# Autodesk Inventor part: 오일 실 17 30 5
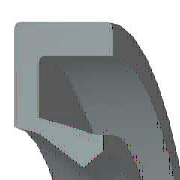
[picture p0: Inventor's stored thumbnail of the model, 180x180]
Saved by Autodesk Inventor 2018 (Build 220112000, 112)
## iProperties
Created: 2012-02
Part Number: 오일 실 17 30 5
Material: 고무
Description: 오일 실 - 스프링 장착, 비스프링, 고무 덮개 G
Document SubType Name: Modeling
Standard: JIS B 2402
Designer: mduedu
Standards Organization: JIS
Language: ko-KR
Size Designation: 17 30 5 A
Categories: <MemberInstance><Categories><Category DisplayName="샤프트 부품" InternalName="7f7aeb1f-a693-4053-b835-cee3144e0d98" Mnemonic="SHFT"><Category DisplayName="실링" Intern
Density: 0.93 g/cm^3
Appearance: 고무 - 검은색 - 버전 1.1
Mass: 1.22959 g
Surface Area: 18.6191 cm^2
Volume: 1.32214 cm^3
IsCustomPart: 1
Author: mduedu
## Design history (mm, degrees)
fillet "모깎기2" dims "d41" = 0.5
fillet "모깎기3" dims "d42" = 0.5
body "Solid1"
revolve "회전1" stored, may be unused: angle "d29" = 360 deg
fillet "모깎기1" dims "d34" = 0.25 (= 0.05 x b)
sketch "스케치2"
  geometry: L1 (9.58, -3.438)-(9.905, -5); L2 (9.147, -3.282)-(9.58, -3.438); L3 (8.5, -1.72)-(9.147, -3.282); L4 (9.682, -1.22)-(8.5, -1.72); L5 (10.811, -3.75)-(9.682, -1.22); L6 (12.111, -3.75)-(10.811, -3.75); L7 (13.556, -1.25)-(12.111, -3.75); L8 (13.556, 0)-(13.556, -1.25); L9 (15, 0)-(13.556, 0); L10 (15, -5)-(15, 0); L11 (9.905, -5)-(15, -5); L12 (0, -9.6)-(0, 1.6) reference; L13 (28, 0)-(14, 0) reference
  constraints: 22 end point, 3 horizontal, 2 vertical
  dimensions: "d2" = 5 distance of L10.start L9.start (= b); "d4" = 1.25 vertical distance of L5.start L1.end (= 0.25 x b); "d6" = 1.44444 distance of L9.start L8.start (= 0.111111 x dd - 0.111111 x Diam); "d8" = 1.25 distance of L8.start L7.start (= 0.25 x b); "d10" = 1.44444 horizontal distance of L7.start L6.start (= 0.111111 x dd - 0.111111 x Diam); "d12" = 1.21951 vertical distance of L9.start L4.start (= 0.243902 x b); "d14" = 1.18182 horizontal distance of L4.start L3.start (= 0.0909091 x dd - 0.0909091 x Diam); "d16" = 0.5 vertical distance of L4.start L3.start (= 0.1 x b); "d18" = 1.3 distance of L6.start L5.start (= 0.1 x dd - 0.1 x Diam); "d20" = 1.5625 vertical distance of L3.start L2.start (= 0.3125 x b); "d22" = 0.64677 horizontal distance of L3.start L2.start (= 0.0497512 x dd - 0.0497512 x Diam); "d24" = 0.325 horizontal distance of L1.start L1.end (= 0.025 x dd - 0.025 x Diam); "d26" = 1.5625 vertical distance of L1.start L1.end (= 0.3125 x b); "d28" = 0.43333 horizontal distance of L2.start L1.start (= 0.0333333 x dd - 0.0333333 x Diam); "d35" = 0 distance between parallel lines of L13 L9; "d36" = 15 distance between parallel lines of L12 L10 (= 0.5 x dd); "d37" = 8.5 distance from line of L12 L3.start (= 0.5 x Diam)
other parameters: "Diam" = 17 [user parameter; used in 8 equation terms], "b" = 5 [user parameter; used in 8 equation terms], "d1" = 8 (derived), "d3" = 2 (derived), "d5" = 2.22222 (derived), "d7" = 2 (derived), "d9" = 2.22222 (derived), "d11" = 1.95122 (derived), "d13" = 1.81818 (derived), "d15" = 0.8 (derived), "d17" = 2 (derived), "d19" = 2.5 (derived), "d21" = 0.99502 (derived), "d23" = 0.5 (derived), "d25" = 2.5 (derived), "d27" = 0.66667 (derived), "d38" = 0
